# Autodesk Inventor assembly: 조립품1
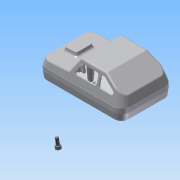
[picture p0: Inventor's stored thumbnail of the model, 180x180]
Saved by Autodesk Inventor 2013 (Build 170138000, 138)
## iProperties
Created: 2015-05
Part Number: 조립품1
Document SubType Name: Assembly
Designer: WINDOWS7
Author: WINDOWS7
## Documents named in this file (7)
- C:\Users\WINDOWS7\Desktop\450508V1007\조립품1.iam
- C:\Users\WINDOWS7\Desktop\450508V1007\M2x4.ipt
- C:\Users\WINDOWS7\Desktop\450508V1007\M4x10.ipt
- C:\Users\WINDOWS7\Desktop\450508V1007\QHSCP.ipt
- C:\Users\WINDOWS7\Desktop\450508V1007\바퀴.ipt
- C:\Users\WINDOWS7\Desktop\450508V1007\바퀴고정부.ipt
- C:\Users\WINDOWS7\Desktop\450508V1007\커버.ipt
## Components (3 placed, 3 different names)
1. M2x4:1
2. M4x10:1
3. QHSCP:1
